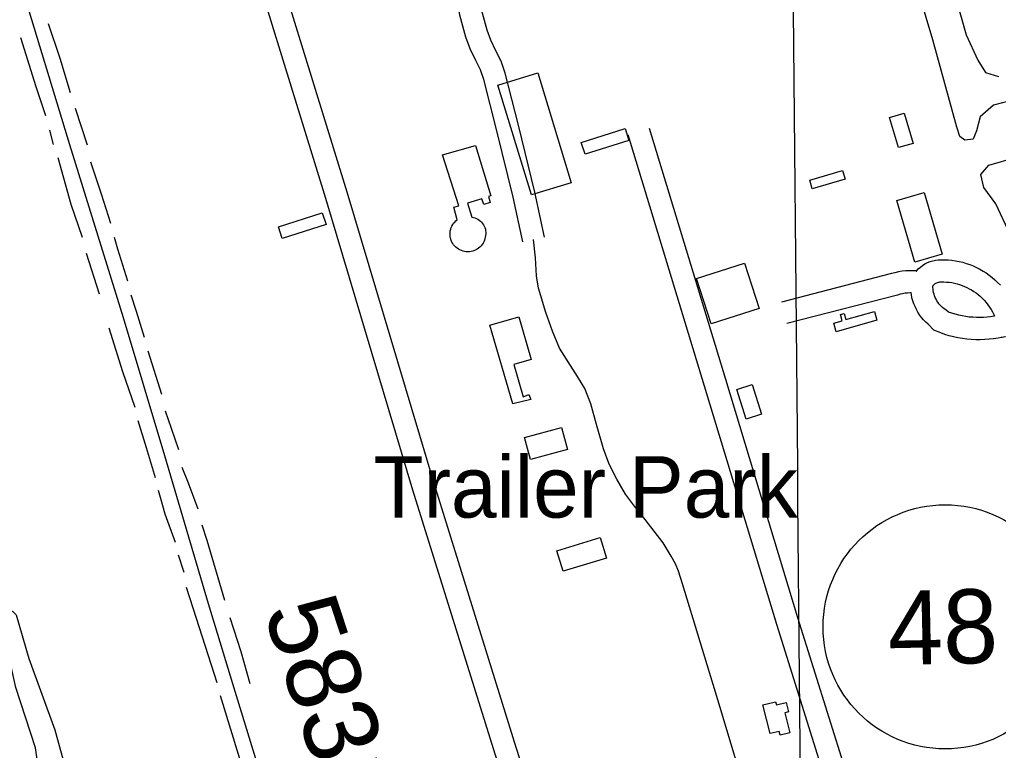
# Model space of a CAD drawing. Extents: x 3598634 to 3636690, y 517270 to 542944.
# Drawn here: x 3606976 to 3608299, y 533703 to 534691 of the extents above; entities that cross this region are included whole.
import ezdxf

# ---------------------------------------------------------------- set-up
doc = ezdxf.new("R2010")
doc.units = 0
for name, color, linetype in [('V-BLDG-OTLN', 7, 'Continuous'), ('V-GRID-MAJR', 7, 'Continuous'), ('V-ROAD-CNTR', 7, 'Continuous'), ('V-ROAD-IDEN', 7, 'Continuous'), ('V-SITE-VEGE', 7, 'Continuous'), ('V-SURV-IDEN', 7, 'Continuous'), ('V-TOPO-GNAM-IDEN', 7, 'Continuous'), ('V-TOPO-SHOR', 7, 'Continuous')]:
    doc.layers.add(name, color=color, linetype=linetype)

msp = doc.modelspace()

# ---------------------------------------------------------------- linework, layer by layer
at = {"layer": 'V-BLDG-OTLN'}
for points in [[(3607668.072, 534454.306), (3607622.889, 534602.821), (3607676.702, 534619.192), (3607721.8850000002, 534470.675)], [(3608164.394, 534518.21), (3608152.258, 534559.086), (3608171.935, 534564.926), (3608184.063, 534524.05)], [(3607740.5924802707, 534509.199955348), (3607735.4694905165, 534525.2689232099), (3607794.638372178, 534544.1328854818), (3607799.761361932, 534528.0649176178)], [(3607592.505, 534521.333), (3607613.411, 534453.206), (3607609.919, 534452.135), (3607612.452, 534443.875), (3607603.703, 534441.188), (3607601.309, 534448.993), (3607581.833, 534443.017), (3607587.632, 534424.116), (3607589.754, 534423.762), (3607591.8310000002, 534423.197), (3607593.84, 534422.4230000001), (3607595.759, 534421.45), (3607597.571, 534420.2880000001), (3607599.259, 534418.947), (3607600.799, 534417.448), (3607602.184, 534415.795), (3607603.396, 534414.015), (3607604.418, 534412.121), (3607605.245, 534410.132), (3607605.8680000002, 534408.0700000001), (3607606.282, 534405.957), (3607606.4760000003, 534403.812), (3607606.4560000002, 534401.66), (3607606.218, 534399.52), (3607605.765, 534397.414), (3607605.29, 534395.235), (3607604.614, 534393.112), (3607603.744, 534391.059), (3607602.6890000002, 534389.095), (3607601.454, 534387.24), (3607600.054, 534385.505), (3607598.4990000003, 534383.908), (3607596.801, 534382.462), (3607594.9790000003, 534381.18), (3607593.045, 534380.074), (3607591.0160000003, 534379.15), (3607588.91, 534378.419), (3607586.7460000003, 534377.887), (3607584.54, 534377.559), (3607582.316, 534377.434), (3607580.088, 534377.518), (3607577.878, 534377.809), (3607575.705, 534378.3), (3607573.585, 534378.995), (3607571.541, 534379.881), (3607569.588, 534380.955), (3607567.74, 534382.204), (3607566.02, 534383.6190000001), (3607564.435, 534385.188), (3607563.003, 534386.898), (3607561.738, 534388.731), (3607560.646, 534390.674), (3607559.739, 534392.712), (3607559.026, 534394.822), (3607558.512, 534396.992), (3607558.201, 534399.2), (3607558.094, 534401.428), (3607558.197, 534403.655), (3607558.506, 534405.862), (3607559.018, 534408.035), (3607559.7260000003, 534410.147), (3607560.63, 534412.185), (3607561.719, 534414.128), (3607562.983, 534415.965), (3607564.412, 534417.675), (3607565.9930000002, 534419.248), (3607567.714, 534420.6630000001), (3607563.202, 534437.588), (3607570.014, 534439.609), (3607547.748, 534508.42)], [(3608092.12, 534475.533), (3608047.839, 534462.723), (3608044.49, 534474.313), (3608088.77, 534487.117)], [(3608186.419, 534363.635), (3608162.148, 534446.747), (3608199.02, 534457.513), (3608223.287, 534374.401)], [(3607331.3332987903, 534395.2551832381), (3607326.2103090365, 534411.3241510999), (3607385.3791906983, 534430.1881133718), (3607390.5021804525, 534414.1201455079)], [(3607956.346, 534362.248), (3607975.911, 534300.931), (3607910.876, 534280.181), (3607891.3140000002, 534341.498)], [(3608135.143, 534284.824), (3608079.963, 534269.324), (3608076.703, 534280.934), (3608088.205, 534284.164), (3608085.847, 534292.557), (3608090.969, 534293.9940000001), (3608093.265, 534285.817), (3608131.823, 534296.643)], [(3607642.9020000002, 534171.708), (3607611.92, 534278.1630000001), (3607651.022, 534289.544), (3607667.752, 534232.059), (3607644.245, 534225.216), (3607657.054, 534181.207), (3607664.707, 534184.617), (3607667.5130000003, 534177.564)], [(3607958.47, 534151.235), (3607945.649, 534191.431), (3607966.375, 534198.04), (3607979.1920000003, 534157.843)], [(3607717.113, 534110.3200000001), (3607667.019, 534096.557), (3607658.878, 534126.196), (3607708.972, 534139.954)], [(3607769.532, 533963.482), (3607711.0840000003, 533945.572), (3607702.593, 533973.286), (3607761.041, 533991.194)], [(3608010.4990000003, 533754.285), (3608017.2290000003, 533727.0380000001), (3608004.423, 533723.876), (3608003.116, 533729.154), (3607990.73, 533726.094), (3607981.1210000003, 533765), (3607998.261, 533769.233), (3607999.278, 533765.117), (3608012.275, 533768.326), (3608015.435, 533755.504)]]:
    msp.add_lwpolyline(points, close=True, dxfattribs=at)
at = {"layer": 'V-GRID-MAJR'}
msp.add_spline([(3608130.468, 522726.087), (3608075.829, 528784.895), (3608021.174, 534845.634), (3607966.518, 540906.389), (3607966.501, 540908.307)], degree=3, dxfattribs=at)
at = {"layer": 'V-ROAD-CNTR'}
for points in [[(3607857.8932456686, 533277.8744180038), (3607837.046287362, 533355.347263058), (3607819.019323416, 533416.0991415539), (3607801.6543581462, 533447.3300790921), (3607769.94242157, 533464.8450440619), (3607735.418490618, 533468.039037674), (3607723.1065152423, 533472.4100289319), (3607714.3255328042, 533501.699970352), (3607647.646666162, 533707.274559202), (3607536.628888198, 534064.1188455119), (3607419.1481231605, 534458.2140573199), (3607287.047387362, 534886.3672010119), (3607065.2836465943, 535688.553838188)], [(3607828.923303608, 533270.078433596), (3607808.1763451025, 533347.1812793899), (3607791.19737906, 533404.4031649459), (3607779.6164022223, 533425.230123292), (3607760.930439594, 533435.5511026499), (3607728.9185036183, 533438.5130967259), (3607698.736563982, 533449.2260753), (3607685.685590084, 533492.7639882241), (3607619.0547233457, 533698.1905773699), (3607507.930945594, 534055.3768629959), (3607390.4401805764, 534449.5060747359), (3607258.249444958, 534877.945217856), (3607036.021011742, 535681.8169978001)], [(3607322.916, 533602.393), (3607267.7120000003, 533782.935), (3607231.833, 533901.436), (3607172.507, 534101.491), (3607116.623, 534288.301), (3607044.159, 534521.822), (3606972.399, 534758.129), (3606906.863, 534979.093), (3606832.3340000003, 535221.675), (3606762.651, 535453.099), (3606719.176, 535594.604)], [(3607685.7726547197, 534397.406675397), (3607672.6681753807, 534458.2421637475), (3607650.564936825, 534548.4357764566), (3607632.509158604, 534618.7050059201), (3607627.133238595, 534634.9851244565), (3607619.8419629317, 534648.9370846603), (3607613.2930700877, 534663.4553744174), (3607608.1808841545, 534676.9852938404), (3607601.037628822, 534703.2573219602), (3607598.514659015, 534721.2850040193), (3607595.205384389, 534770.9647340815), (3607592.4770631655, 534807.0639295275), (3607588.8764597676, 534832.0477297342), (3607582.9783326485, 534855.1725405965), (3607576.0559397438, 534874.0313027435), (3607573.1021699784, 534885.3850964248), (3607569.5334515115, 534924.0281626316)], [(3607656.4453452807, 534391.0893246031), (3607643.4298246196, 534451.5118362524), (3607621.467063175, 534541.1322235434), (3607603.7048413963, 534610.2589940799), (3607599.412761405, 534623.2568755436), (3607592.8520370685, 534635.8109153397), (3607585.5609299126, 534651.9746255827), (3607579.6091158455, 534667.7267061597), (3607571.590371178, 534697.2186780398), (3607568.6533409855, 534718.2049959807), (3607565.280615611, 534768.8372659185), (3607562.6389368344, 534803.7900704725), (3607559.4115402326, 534826.1842702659), (3607554.287667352, 534846.2734594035), (3607547.3900602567, 534865.0646972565), (3607546.3170998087, 534869.1889765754)], [(3608141.43167859, 533528.521916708), (3608113.055735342, 533612.122749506), (3608028.434904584, 533882.471208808), (3607930.70710004, 534204.7225643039), (3607827.55230635, 534544.226885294)], [(3608113.023735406, 533518.8799359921), (3608084.53179239, 533602.8187681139), (3607999.764961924, 533873.637226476), (3607902.0011574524, 534196.0085817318), (3607798.848363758, 534535.5049027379)], [(3607977.33, 533581.301), (3607920.066, 533771.5970000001), (3607872.4560000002, 533928.437), (3607866.933, 533945.863), (3607862.781, 533955.628), (3607857.239, 533966.089), (3607846.147, 533984.228), (3607821.86, 534015.639), (3607807.287, 534033.79), (3607795.492, 534049.84), (3607783.71, 534070.072), (3607773.321, 534090.2980000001), (3607765.718, 534111.215), (3607756.062, 534143.974), (3607748.48, 534171.856), (3607740.182, 534192.772), (3607730.4760000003, 534208.818), (3607706.21, 534247.194), (3607696.525, 534270.205), (3607687.542, 534295.303), (3607677.886, 534328.0650000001), (3607675.148, 534344.787), (3607673.823, 534369.166), (3607671.109, 534394.248)], [(3608188.309924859, 534351.2346777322), (3608188.446812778, 534351.4115513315), (3608191.016272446, 534354.1980623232), (3608193.8337711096, 534356.7578909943), (3608196.854904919, 534359.0516299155), (3608200.0541795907, 534361.0700564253), (3608203.4286099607, 534362.808492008), (3608206.947384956, 534364.246040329), (3608210.5744144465, 534365.3668719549), (3608214.2817151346, 534366.1679546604), (3608218.0423791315, 534366.640138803), (3608221.466906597, 534366.7712674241), (3608226.412895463, 534366.7666600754), (3608231.418613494, 534366.5229621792), (3608236.398276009, 534366.0431630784), (3608241.352530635, 534365.330421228), (3608246.266592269, 534364.3834830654), (3608251.1304343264, 534363.2074044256), (3608255.9360063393, 534361.8017483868), (3608260.6674198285, 534360.1702666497), (3608265.315346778, 534358.3201774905), (3608269.8742731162, 534356.2504808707), (3608274.3304152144, 534353.9670721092), (3608278.6730006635, 534351.4766086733), (3608282.88913426, 534348.7862029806), (3608286.9789717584, 534345.8973402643), (3608290.924964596, 534342.8193027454), (3608294.72082166, 534339.560057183), (3608298.3430874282, 534336.1417974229), (3608302.056701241, 534332.3132821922)], [(3608188.631867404, 534351.6122381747), (3608183.993156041, 534351.8809542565), (3608179.0046544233, 534351.8929718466), (3608174.0210366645, 534351.6247249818), (3608169.064132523, 534351.0782284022), (3608164.149280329, 534350.259486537), (3608159.2784077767, 534349.1665161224), (3608155.0538219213, 534347.9650866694), (3608006.073920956, 534309.4321165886)], [(3608210.75271639, 534331.2169824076), (3608211.3791872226, 534332.0264486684), (3608212.171727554, 534332.8859376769), (3608213.0282288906, 534333.6641090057), (3608213.961095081, 534334.3723700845), (3608214.9558204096, 534334.9999435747), (3608215.9953900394, 534335.535507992), (3608217.068615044, 534335.973959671), (3608218.1855855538, 534336.3191280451), (3608219.3282848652, 534336.5660453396), (3608220.4896208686, 534336.711861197), (3608222.0270934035, 534336.7707325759), (3608225.669104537, 534336.7673399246), (3608229.249386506, 534336.5930378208), (3608232.821723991, 534336.2488369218), (3608236.375469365, 534335.7375787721), (3608239.899407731, 534335.0585169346), (3608243.389565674, 534334.2145955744), (3608246.829993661, 534333.2082516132), (3608250.2245801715, 534332.0377333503), (3608253.5606532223, 534330.7098225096), (3608256.825726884, 534329.2275191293), (3608260.0195847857, 534327.5909278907), (3608263.132999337, 534325.8053913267), (3608266.15686574, 534323.8757970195), (3608269.0890282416, 534321.8046597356), (3608271.917035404, 534319.5986972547), (3608274.64317834, 534317.2579428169), (3608277.270912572, 534314.7782025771), (3608280.021298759, 534311.9427178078), (3608282.61714437, 534308.9958536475), (3608285.0722439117, 534305.9269792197), (3608287.37809253, 534302.7458561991), (3608289.530361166, 534299.4590780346), (3608291.522063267, 534296.074453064), (3608293.3508786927, 534292.5979265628), (3608294.218558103, 534290.3792686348)], [(3608181.3893843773, 534321.8871398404), (3608179.775345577, 534321.8910281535), (3608176.4729633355, 534321.7132750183), (3608173.1758674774, 534321.3497715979), (3608169.9027196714, 534320.804513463), (3608166.6715922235, 534320.0794838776), (3608162.9141780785, 534319.0109133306), (3608013.5860790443, 534280.3878834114)], [(3608204.2838356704, 534279.4044038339), (3608201.149818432, 534282.3131915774), (3608198.2016718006, 534285.41104878), (3608195.4521331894, 534288.6879663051), (3608192.9143748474, 534292.1257658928), (3608190.594318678, 534295.7132838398), (3608188.4996244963, 534299.4432982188), (3608186.63903408, 534303.3003072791), (3608185.0283670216, 534307.2598104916), (3608183.665770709, 534311.3029032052), (3608182.5524775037, 534315.4383582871), (3608181.7039599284, 534319.6284737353), (3608181.3393759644, 534322.2462024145)], [(3608228.199761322, 534298.8306342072), (3608225.866642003, 534300.5082089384), (3608224.0041643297, 534302.0315961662), (3608222.240181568, 534303.6688084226), (3608220.5803281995, 534305.4129512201), (3608219.033866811, 534307.256033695), (3608217.601625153, 534309.1962341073), (3608216.293681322, 534311.2187161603), (3608215.1143755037, 534313.3187017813), (3608214.0709659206, 534315.4816927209), (3608213.1636329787, 534317.7121895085), (3608212.392229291, 534320.0010967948), (3608211.767522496, 534322.3216417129), (3608211.2900400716, 534324.6795262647), (3608210.957649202, 534327.0661071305), (3608210.7763663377, 534329.461630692), (3608210.75271639, 534331.2169824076)], [(3608294.1954122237, 534290.4965132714), (3608293.651732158, 534290.3891825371), (3608288.875915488, 534289.647066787), (3608284.070234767, 534289.0997753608), (3608279.2496839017, 534288.7462505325), (3608274.4184986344, 534288.5900049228), (3608269.588734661, 534288.6299349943), (3608264.7597874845, 534288.8688071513), (3608259.9408474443, 534289.3015609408), (3608255.1461050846, 534289.929782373), (3608250.385287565, 534290.7489909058), (3608245.6624454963, 534291.7648943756), (3608240.978395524, 534292.9721329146), (3608236.349100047, 534294.3657178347), (3608232.1083173, 534295.8342836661), (3608228.199761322, 534298.8306342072)], [(3608309.007175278, 534262.6438101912), (3608308.0447440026, 534262.3334837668), (3608304.4678939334, 534261.7260467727), (3608303.221310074, 534261.6993588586), (3608298.8622678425, 534260.8388174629), (3608292.878084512, 534259.908933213), (3608286.865765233, 534259.2242246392), (3608280.8323160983, 534258.7817494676), (3608274.779501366, 534258.5859950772), (3608268.723265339, 534258.6360650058), (3608262.676212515, 534258.9351928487), (3608256.649152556, 534259.4764390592), (3608250.651894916, 534260.262217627), (3608244.6847124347, 534261.2890090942), (3608238.761554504, 534262.5631056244), (3608232.907604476, 534264.0718670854), (3608227.1128999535, 534265.8162821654), (3608221.3901944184, 534267.7980318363), (3608212.054433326, 534271.464138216), (3608204.2838356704, 534279.4044038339)]]:
    msp.add_lwpolyline(points, dxfattribs=at)
at = {"layer": 'V-ROAD-IDEN'}
msp.add_circle((3608227.4155066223, 533870.446232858), 164.99966999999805, dxfattribs=at)
at = {"layer": 'V-SITE-VEGE'}
for points in [[(3608315.549, 534881.332), (3608282.208, 534988.545), (3608269.954, 535026.3470000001), (3608258.348, 535049.727), (3608243.267, 535058.6950000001), (3608225.412, 535058.058), (3608173.881, 535046.532), (3608153.2630000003, 535040.411), (3608148.43, 535031.498), (3608151.8340000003, 535020.502), (3608182.46, 534924.283), (3608235.503, 534742.855), (3608255.897, 534670.697), (3608271.593, 534636.3200000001), (3608281.845, 534619.811), (3608299.683, 534614.267)], [(3608313.323, 534581.269), (3608292.708, 534575.836), (3608274.808, 534560.091), (3608269.948, 534540.879), (3608265.111, 534529.906), (3608254.119, 534528.564), (3608247.267, 534533.389), (3608243.183, 534545.761), (3608210.558, 534663.96), (3608173.15, 534789.725)], [(3607000.639, 533688.227), (3606997.946, 533706.7710000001), (3606971.397, 533788.56), (3606957.1580000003, 533851.774), (3606953.117, 533879.25), (3606959.322, 533888.159), (3606966.884, 533891.571), (3606971.674, 533886.752), (3606988.676, 533827.651), (3607024.109, 533731.417), (3607034.978, 533690.187)]]:
    msp.add_lwpolyline(points, dxfattribs=at)
msp.add_lwpolyline([(3608389.6210000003, 534517.4720000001), (3608385.468, 534506.4990000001), (3608371.687, 534488.686), (3608355.163, 534473.625), (3608341.389, 534458.557), (3608338.5870000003, 534439.339), (3608339.875, 534409.123), (3608338.4620000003, 534395.393), (3608328.828, 534388.555), (3608315.131, 534400.953), (3608296.021, 534442.206), (3608279.605, 534464.226), (3608275.535, 534482.091), (3608286.558, 534494.42), (3608323.667, 534505.301), (3608360.785, 534518.928), (3608377.286, 534525.748), (3608385.5270000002, 534527.098)], close=True, dxfattribs=at)
at = {"layer": 'V-TOPO-SHOR'}
for p, q in [((3607067.907, 534521.74), (3607052.029, 534571.234)), ((3607022.042, 534522.428), (3607017.224, 534541.944)), ((3607084.15, 534320.276), (3607066.896, 534375.3470000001)), ((3607168.632, 534184.365), (3607149.9930000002, 534242.921)), ((3607198.693, 533943.86), (3607191.099, 533967.562)), ((3607273.8910000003, 533692.2220000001), (3607247.669, 533777.268))]:
    msp.add_line(p, q, dxfattribs=at)
for points in [[(3607045.123, 534592.148), (3607031.328, 534638.849), (3607015.4420000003, 534685.56)], [(3607011.7060000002, 534561.459), (3606998.585, 534600.498), (3606977.879, 534666.7220000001)], [(3607061.3850000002, 534396.954), (3607046.19, 534441.569), (3607028.2600000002, 534504.302)], [(3607099.643, 534415.787), (3607087.22, 534455.522), (3607072.716, 534498.743)], [(3607122.4050000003, 534337.719), (3607109.295, 534380.936), (3607104.464, 534396.97)], [(3607145.1720000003, 534261.741), (3607134.127, 534296.593), (3607127.228, 534318.9)], [(3607132.467, 534166.916), (3607115.8880000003, 534215.022), (3607097.251, 534274.272)], [(3607191.404, 534109.779), (3607181.733, 534138.363), (3607173.4450000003, 534162.064)], [(3607160.055, 534072.12), (3607147.634, 534112.55), (3607136.593, 534148.797)], [(3607217.6410000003, 534029.612), (3607204.507, 534064.471), (3607196.211, 534086.086)], [(3607186.968, 533984.29), (3607173.148, 534022.634), (3607167.633, 534042.15), (3607164.186, 534054.698)], [(3607253.505, 533906.234), (3607230.056, 533987.091), (3607223.1520000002, 534008.006)], [(3607243.54, 533794.6900000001), (3607215.232, 533881.828), (3607202.119, 533923.653)], [(3607288.008, 533793.31), (3607275.595, 533836.527), (3607261.099, 533882.535)]]:
    msp.add_lwpolyline(points, dxfattribs=at)

# ---------------------------------------------------------------- texts
at = {"layer": 'V-ROAD-IDEN'}
msp.add_text('48', height=99.99970600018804, rotation=1.198985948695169, dxfattribs=at).set_placement((3608150.919659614, 533818.834336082))
at = {"layer": 'V-SURV-IDEN'}
msp.add_text('5831+94.7', height=100, rotation=288.19142527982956, dxfattribs=at).set_placement((3607305.328817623, 533892.093757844))
at = {"layer": 'V-TOPO-GNAM-IDEN'}
msp.add_text('Trailer Park', height=82.99983200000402, dxfattribs=at).set_placement((3607454.5696462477, 534018.107185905))

doc.saveas('drawing.dxf')
